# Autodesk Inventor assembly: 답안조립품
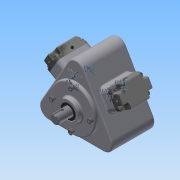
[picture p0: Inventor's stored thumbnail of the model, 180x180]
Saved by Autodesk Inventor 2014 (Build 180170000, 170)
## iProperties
Created: 2015-06
Part Number: 답안조립품
Document SubType Name: Assembly
Designer: Administrator
Mass: 5318.58 g
Surface Area: 2414.93 cm^2
Volume: 1564.62 cm^3
Density: 3.39928 g/cm^3
Author: Administrator
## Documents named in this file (20)
- C:\Users\Administrator\Desktop\350605V1051\답안조립품.iam
- C:\Users\Administrator\Desktop\350605V1051\본체.ipt
- C:\Users\Administrator\Desktop\350605V1051\베어링 NA 4904.ipt
- 베어링 NA 4904.ipt
- C:\Users\Administrator\Desktop\350605V1051\편심축.ipt
- C:\Users\Administrator\Desktop\350605V1051\앞커버.ipt
- C:\Users\Administrator\Desktop\350605V1051\오일실.ipt
- 오일실.ipt
- C:\Users\Administrator\Desktop\350605V1051\M6x0.7x20.ipt
- M6x0.7x20.ipt
- C:\Users\Administrator\Desktop\350605V1051\부시.ipt
- C:\Users\Administrator\Desktop\350605V1051\슬라이드.ipt
- C:\Users\Administrator\Desktop\350605V1051\헤더커버.ipt
- 헤더커버.ipt
- C:\Users\Administrator\Desktop\350605V1051\M4x0.5x16.ipt
- M4x0.5x16.ipt
- C:\Users\Administrator\Desktop\350605V1051\8 - 스프링.ipt
- C:\Users\Administrator\Desktop\350605V1051\9 - 스프링.ipt
- C:\Users\Administrator\Desktop\350605V1051\10 - 스프링.ipt
- C:\Users\Administrator\Desktop\350605V1051\11 - 스프링.ipt
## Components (18 placed, 7 different names)
1. 헤더커버:1
2. M4x0.5x16:1
3. M4x0.5x16:2
4. M4x0.5x16:3
5. M4x0.5x16:4
6. M4x0.5x16:5
7. M4x0.5x16:6
8. M4x0.5x16:7
9. M4x0.5x16:8
10. 헤더커버:2
11. 8 - 스프링:1
12. 9 - 스프링:1
13. 10 - 스프링:1
14. 11 - 스프링:1
15. M6x0.7x20:1
16. M6x0.7x20:2
17. M6x0.7x20:3
18. M6x0.7x20:4
